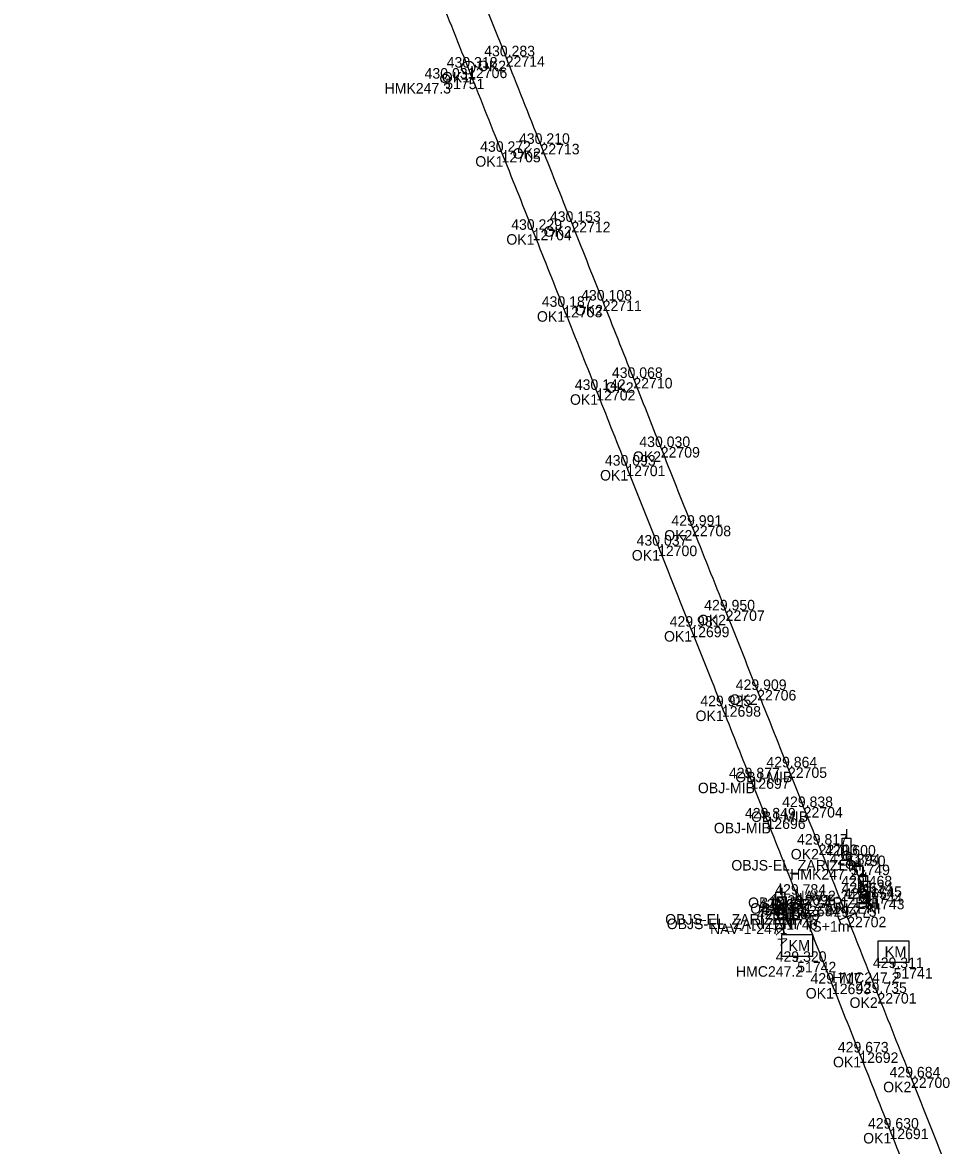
# Model space of a CAD drawing. Extents: x -678609 to -677678, y -1092434 to -1090394.
# Drawn here: x -678173.6 to -678067.3, y -1092180.5 to -1092052.4 of the extents above; entities that cross this region are included whole.
import ezdxf

# ---------------------------------------------------------------- set-up
doc = ezdxf.new("R2010")
doc.units = 0
for name, color, linetype in [('Vrstva 1', 7, 'Continuous'), ('Vrstva 3', 7, 'Continuous'), ('Vrstva 50', 7, 'Continuous'), ('Vrstva 6', 7, 'Continuous'), ('Vrstva 60', 7, 'Continuous'), ('Vrstva 61', 7, 'Continuous'), ('Vrstva 62', 7, 'Continuous'), ('Vrstva 7', 7, 'Continuous')]:
    doc.layers.add(name, color=color, linetype=linetype)

msp = doc.modelspace()

# ---------------------------------------------------------------- linework, layer by layer
at = {"layer": 'Vrstva 1'}
for points in [[(-677965.5, -1092428.88), (-677967.8, -1092425.54), (-677972.06, -1092419.07), (-677977.32, -1092410.57), (-677981.84, -1092402.75), (-677986.7, -1092393.7), (-677991.48, -1092384.16), (-677995.99, -1092374.55), (-678000.17, -1092365.13), (-678004.02, -1092356.1), (-678007.82, -1092346.9), (-678011.74, -1092337.16), (-678015.49, -1092327.76), (-678018.88, -1092319.21), (-678022.34, -1092310.49), (-678025.4, -1092302.78), (-678026.46, -1092300.1), (-678028.08, -1092296.04), (-678031.51, -1092287.37), (-678035.08, -1092278.36), (-678038.67, -1092269.33), (-678042.19, -1092260.44), (-678045.92, -1092251.04), (-678049.17, -1092242.84), (-678052.72, -1092233.88), (-678056.52, -1092224.29), (-678060.13, -1092215.17), (-678063.85, -1092205.78), (-678067.58, -1092196.38), (-678071.23, -1092187.17), (-678074.63, -1092178.59), (-678078.07, -1092169.9), (-678081.19, -1092162.05), (-678084.71, -1092153.16), (-678085.21, -1092151.9), (-678088.66, -1092143.2), (-678090.49, -1092138.62), (-678093.75, -1092130.39), (-678097.35, -1092121.32), (-678101.03, -1092112.07), (-678104.65, -1092102.94), (-678108.08, -1092094.3), (-678111.85, -1092084.82), (-678115.34, -1092076.03), (-678118.88, -1092067.13), (-678122.7, -1092057.52), (-678126.45, -1092048.08), (-678130.12, -1092038.85), (-678134.04, -1092029), (-678137.7, -1092019.78), (-678141.32, -1092010.68), (-678144.94, -1092001.55), (-678148.54, -1091992.51), (-678152.22, -1091983.22), (-678155.78, -1091974.26), (-678159.37, -1091965.23), (-678163.15, -1091955.67), (-678166.8, -1091946.49), (-678170.64, -1091936.84), (-678174.45, -1091927.39), (-678178.21, -1091918.23), (-678182.03, -1091909.19), (-678185.86, -1091900.36), (-678190.3, -1091890.41), (-678194.61, -1091881.04), (-678198.42, -1091872.99), (-678201.55, -1091866.52), (-678205.76, -1091857.98), (-678210.04, -1091849.52), (-678214.14, -1091841.6), (-678218.68, -1091833.02), (-678223.39, -1091824.3), (-678228.11, -1091815.74), (-678232.89, -1091807.24), (-678237.68, -1091798.82), (-678242.57, -1091790.27), (-678247.48, -1091781.7), (-678252.5, -1091772.96), (-678257.41, -1091764.41), (-678262.3, -1091755.91), (-678267.38, -1091747.08), (-678272.06, -1091738.95), (-678276.67, -1091730.93), (-678281, -1091723.4), (-678285.64, -1091715.33), (-678290.57, -1091706.75), (-678295.17, -1091698.74), (-678299.18, -1091691.75), (-678304.61, -1091682.28), (-678309.18, -1091674.33), (-678309.94, -1091673.01), (-678310.56, -1091671.92), (-678316.58, -1091661.44), (-678321.55, -1091652.79), (-678326.07, -1091644.94), (-678331.1, -1091636.19), (-678336.13, -1091627.42), (-678341.16, -1091618.67), (-678346.24, -1091609.83), (-678351.2, -1091601.19), (-678356.26, -1091592.39), (-678361.27, -1091583.68), (-678366.29, -1091574.95), (-678371.38, -1091566.09), (-678376.48, -1091557.23), (-678380.94, -1091549.47), (-678384.95, -1091542.5), (-678389.88, -1091533.92), (-678391.41, -1091531.24), (-678395.31, -1091524.46), (-678398.31, -1091519.22), (-678402.19, -1091512.46), (-678406.98, -1091504.09), (-678412.06, -1091495.21), (-678417.07, -1091486.44), (-678421.59, -1091478.47), (-678426.39, -1091469.86), (-678431.19, -1091461.01), (-678435.59, -1091452.6), (-678440.54, -1091442.69), (-678444.84, -1091433.53), (-678448.93, -1091424.07), (-678452.67, -1091414.65), (-678456.15, -1091404.93), (-678459.23, -1091395.35), (-678461.83, -1091386.29), (-678463.33, -1091380.53), (-678465.42, -1091371.56), (-678467.31, -1091362.18), (-678468.87, -1091352.97), (-678470.15, -1091343.72), (-678471.15, -1091334.55), (-678471.89, -1091325.25), (-678472.38, -1091315.14), (-678472.53, -1091305.81), (-678472.39, -1091295.81), (-678471.98, -1091285.84), (-678471.34, -1091275.9), (-678470.53, -1091266.07), (-678469.61, -1091256.67), (-678468.46, -1091246.14), (-678467.2, -1091235.36), (-678466.06, -1091225.73), (-678464.97, -1091216.57), (-678463.79, -1091206.63), (-678462.6, -1091196.46), (-678461.48, -1091186.51), (-678460.53, -1091177.26), (-678460.07, -1091172.27), (-678459.6, -1091166.76), (-678458.93, -1091157.15), (-678458.54, -1091149.43), (-678458.26, -1091139.81), (-678458.24, -1091130.03), (-678458.46, -1091121.76), (-678458.96, -1091112.72), (-678459.56, -1091105.42), (-678460.03, -1091100.7), (-678460.44, -1091097.18), (-678461.42, -1091089.83), (-678462.92, -1091080.59), (-678464.88, -1091070.5), (-678465.87, -1091066.01), (-678468.24, -1091056.34), (-678470.96, -1091046.62), (-678473.78, -1091037.66), (-678476.99, -1091028.33), (-678480.32, -1091019.35), (-678483.95, -1091010.17), (-678487.77, -1091000.93), (-678492.09, -1090990.94), (-678495.91, -1090982.33), (-678497.23, -1090979.39), (-678500.62, -1090971.85), (-678504.73, -1090962.75), (-678508.48, -1090954.44), (-678512.89, -1090944.72), (-678517.19, -1090935.17), (-678521.19, -1090926.12), (-678525.01, -1090917.23), (-678528.92, -1090907.75), (-678532.48, -1090898.64), (-678535.33, -1090890.88), (-678536.98, -1090886.19), (-678540.17, -1090876.47), (-678543.06, -1090866.93), (-678545.5, -1090858.15), (-678547.9, -1090848.75), (-678550.22, -1090838.91), (-678552.41, -1090829.04), (-678553.21, -1090825.32), (-678554.73, -1090818.04), (-678556.89, -1090807.48), (-678558.82, -1090797.84), (-678560.45, -1090789.69), (-678561.92, -1090782.3), (-678563.92, -1090772.26), (-678565.62, -1090763.66), (-678567.4, -1090754.78), (-678569.24, -1090745.59), (-678571.09, -1090736.37), (-678573.01, -1090726.79), (-678574.94, -1090717.24), (-678576.9, -1090707.5), (-678578.79, -1090698.06), (-678580.69, -1090688.61), (-678582.63, -1090679), (-678584.57, -1090669.32), (-678586.61, -1090659.12), (-678588.6, -1090649.18), (-678590.47, -1090639.75), (-678592.41, -1090629.68), (-678594.08, -1090620.48), (-678595.57, -1090611.73), (-678596.96, -1090602.7), (-678598.18, -1090593.61), (-678598.92, -1090587.15), (-678599.86, -1090577.04), (-678600.45, -1090567.62), (-678600.74, -1090558.34), (-678600.75, -1090549.35), (-678600.47, -1090539.84), (-678599.88, -1090530.15), (-678599.15, -1090521.99), (-678598.15, -1090513.61), (-678597.58, -1090509.5), (-678596.28, -1090501.33), (-678594.49, -1090491.96), (-678592.38, -1090482.44), (-678589.8, -1090472.45), (-678586.94, -1090462.72), (-678583.68, -1090452.87), (-678579.95, -1090442.85), (-678576.03, -1090433.29), (-678571.81, -1090423.92), (-678567.43, -1090415), (-678562.94, -1090406.55), (-678558.47, -1090398.73), (-678556.06, -1090394.72)], [(-677960.41, -1092428.88), (-677963.18, -1092424.89), (-677968.58, -1092416.71), (-677973.83, -1092408.16), (-677978.65, -1092399.73), (-677983.17, -1092391.19), (-677987.58, -1092382.29), (-677991.66, -1092373.51), (-677995.54, -1092364.73), (-677999.48, -1092355.45), (-678003, -1092346.86), (-678006.4, -1092338.41), (-678008.07, -1092334.22), (-678011.06, -1092326.67), (-678014.79, -1092317.28), (-678018.17, -1092308.77), (-678021.37, -1092300.71), (-678022.15, -1092298.75), (-678025.47, -1092290.39), (-678029, -1092281.48), (-678032.79, -1092271.95), (-678036.42, -1092262.78), (-678040.08, -1092253.55), (-678043.64, -1092244.58), (-678046.8, -1092236.63), (-678050.2, -1092228.09), (-678054.05, -1092218.4), (-678057.87, -1092208.77), (-678061.64, -1092199.28), (-678064.93, -1092190.99), (-678068.51, -1092181.96), (-678072.17, -1092172.75), (-678076, -1092163.12), (-678079.45, -1092154.42), (-678082.71, -1092146.18), (-678084.42, -1092141.9), (-678086.21, -1092137.37), (-678089.72, -1092128.54), (-678093.32, -1092119.46), (-678097.16, -1092109.8), (-678100.72, -1092100.82), (-678103.85, -1092092.93), (-678107.35, -1092084.1), (-678110.92, -1092075.12), (-678114.45, -1092066.22), (-678118.41, -1092056.23), (-678122.02, -1092047.13), (-678125.64, -1092038.01), (-678129.26, -1092028.91), (-678132.87, -1092019.79), (-678136.68, -1092010.21), (-678140.28, -1092001.13), (-678143.89, -1091992.04), (-678147.54, -1091982.83), (-678151.47, -1091972.91), (-678155.19, -1091963.55), (-678158.5, -1091955.23), (-678162.14, -1091946.1), (-678165.94, -1091936.55), (-678169.61, -1091927.42), (-678172.98, -1091919.18), (-678176.44, -1091910.89), (-678180.32, -1091901.84), (-678184.49, -1091892.39), (-678188.93, -1091882.59), (-678193.21, -1091873.41), (-678197.78, -1091863.91), (-678202.15, -1091855.03), (-678206.56, -1091846.3), (-678211.05, -1091837.64), (-678215.66, -1091828.96), (-678220.33, -1091820.38), (-678225.04, -1091811.91), (-678229.83, -1091803.42), (-678234.98, -1091794.42), (-678239.05, -1091787.33), (-678241.84, -1091782.5), (-678246.33, -1091774.68), (-678251.23, -1091766.16), (-678256.35, -1091757.27), (-678261.45, -1091748.4), (-678266.63, -1091739.38), (-678271.03, -1091731.75), (-678275.99, -1091723.11), (-678281.08, -1091714.25), (-678285.98, -1091705.75), (-678290.88, -1091697.22), (-678295.45, -1091689.28), (-678300.01, -1091681.35), (-678300.91, -1091679.77), (-678305.04, -1091672.59), (-678308.7, -1091666.23), (-678313.56, -1091657.79), (-678316.07, -1091653.42), (-678316.99, -1091651.81), (-678322.04, -1091643.03), (-678327.11, -1091634.21), (-678332.27, -1091625.24), (-678337.32, -1091616.47), (-678342.33, -1091607.74), (-678347.33, -1091599.07), (-678352.43, -1091590.19), (-678357.51, -1091581.37), (-678362.52, -1091572.64), (-678367.56, -1091563.89), (-678372.6, -1091555.12), (-678377.69, -1091546.26), (-678382.67, -1091537.58), (-678387.77, -1091528.7), (-678389.17, -1091526.27), (-678390.17, -1091524.53), (-678393.18, -1091519.29), (-678397.89, -1091511.08), (-678402.8, -1091502.52), (-678408.01, -1091493.44), (-678412.94, -1091484.8), (-678417.67, -1091476.44), (-678422.72, -1091467.34), (-678425.17, -1091462.84), (-678430.24, -1091453.27), (-678432.13, -1091449.6), (-678436.36, -1091441.06), (-678440.36, -1091432.52), (-678444.3, -1091423.5), (-678448.14, -1091413.92), (-678451.67, -1091404.2), (-678454.52, -1091395.48), (-678456.78, -1091387.89), (-678459.36, -1091378.14), (-678461.46, -1091369.04), (-678463.24, -1091360.11), (-678464.77, -1091350.94), (-678466.09, -1091341.11), (-678467.05, -1091331.45), (-678467.74, -1091321.16), (-678468.06, -1091312.46), (-678468.13, -1091302.67), (-678467.92, -1091292.89), (-678467.75, -1091288.5), (-678467.24, -1091279.36), (-678466.65, -1091271.3), (-678465.8, -1091261.65), (-678464.83, -1091252.21), (-678464.22, -1091246.73), (-678463.17, -1091237.54), (-678462.04, -1091228.08), (-678460.89, -1091218.47), (-678459.79, -1091209.09), (-678458.69, -1091199.72), (-678457.61, -1091190.23), (-678456.66, -1091181.26), (-678456.28, -1091177.45), (-678455.95, -1091173.93), (-678455.21, -1091164.81), (-678454.58, -1091155.4), (-678454.12, -1091145.39), (-678453.9, -1091135.42), (-678453.98, -1091125.41), (-678454.4, -1091115.15), (-678455.19, -1091104.66), (-678455.67, -1091099.79), (-678456.77, -1091090.92), (-678457.24, -1091087.61), (-678458, -1091082.76), (-678459.78, -1091072.93), (-678461.55, -1091064.59), (-678463.75, -1091055.56), (-678466.3, -1091046.3), (-678469.14, -1091037.12), (-678472.3, -1091027.84), (-678475.73, -1091018.55), (-678479.35, -1091009.34), (-678482.78, -1091001.05), (-678486.39, -1090992.59), (-678490.2, -1090983.9), (-678491.75, -1090980.39), (-678492.98, -1090977.64), (-678496.18, -1090970.51), (-678500.43, -1090961.06), (-678504.03, -1090953.05), (-678508.11, -1090943.95), (-678512.14, -1090934.91), (-678516.17, -1090925.76), (-678520.15, -1090916.48), (-678524.11, -1090906.91), (-678527.45, -1090898.46), (-678529.96, -1090891.82), (-678532.42, -1090885.01), (-678535.4, -1090876.25), (-678538.3, -1090867), (-678541.15, -1090857.05), (-678543.63, -1090847.53), (-678545.8, -1090838.5), (-678548.27, -1090827.42), (-678548.84, -1090824.71), (-678550.27, -1090817.89), (-678552.12, -1090808.75), (-678554.09, -1090798.9), (-678556.12, -1090788.74), (-678556.56, -1090786.52), (-678557.74, -1090780.65), (-678559.41, -1090772.28), (-678561.24, -1090763.16), (-678563.16, -1090753.57), (-678565.21, -1090743.33), (-678567.13, -1090733.77), (-678569.13, -1090723.69), (-678570.72, -1090715.75), (-678572.44, -1090707.11), (-678574.33, -1090697.58), (-678575.5, -1090691.73), (-678576.87, -1090684.87), (-678578.68, -1090675.8), (-678580.42, -1090667.12), (-678582.34, -1090657.49), (-678584.31, -1090647.61), (-678586.28, -1090637.64), (-678588.2, -1090627.59), (-678589.96, -1090617.89), (-678591.58, -1090608.06), (-678593.06, -1090598.01), (-678594.31, -1090587.86), (-678595.29, -1090577.74), (-678595.95, -1090567.92), (-678596.27, -1090558.34), (-678596.28, -1090548.9), (-678595.99, -1090539.16), (-678595.39, -1090529.68), (-678594.52, -1090520.33), (-678593.84, -1090514.64), (-678593.37, -1090511.09), (-678591.87, -1090501.55), (-678590.51, -1090494.26), (-678588.64, -1090485.54), (-678587.94, -1090482.56), (-678585.53, -1090473.2), (-678582.78, -1090463.82), (-678579.92, -1090455.12), (-678576.62, -1090446.03), (-678572.81, -1090436.54), (-678568.84, -1090427.54), (-678564.34, -1090418.19), (-678559.62, -1090409.18), (-678555.08, -1090401.15), (-678551.2, -1090394.72)]]:
    msp.add_spline(points, degree=3, dxfattribs=at)
at = {"layer": 'Vrstva 3'}
for p, q in [((-678085.83, -1092153.06), (-678085.46, -1092153.99)), ((-678083.78, -1092152.79), (-678085.64, -1092153.52)), ((-678083.97, -1092152.32), (-678083.6, -1092153.25)), ((-678080.56, -1092154.32), (-678080.19, -1092155.25)), ((-678078.52, -1092154.05), (-678080.38, -1092154.79)), ((-678078.7, -1092153.59), (-678078.33, -1092154.52))]:
    msp.add_line(p, q, dxfattribs=at)
at = {"layer": 'Vrstva 50'}
for p, q in [((-678079.54, -1092144.44), (-678079.54, -1092145.44)), ((-678079.49, -1092147.44), (-678079.59, -1092147.44)), ((-678077.63, -1092148.72), (-678077.63, -1092149.72)), ((-678077.38, -1092149.37), (-678077.38, -1092150.37)), ((-678087.09, -1092150.61), (-678087.09, -1092151.61)), ((-678086.91, -1092151.13), (-678086.91, -1092152.13)), ((-678077.58, -1092151.72), (-678077.68, -1092151.72)), ((-678077.33, -1092152.37), (-678077.43, -1092152.37)), ((-678087.04, -1092153.61), (-678087.14, -1092153.61)), ((-678086.86, -1092154.13), (-678086.96, -1092154.13))]:
    msp.add_line(p, q, dxfattribs=at)
for points in [[(-678080.05, -1092147.44), (-678080.04, -1092145.44), (-678079.03, -1092145.44), (-678079.03, -1092147.44)], [(-678078.13, -1092151.72), (-678078.13, -1092149.72), (-678077.12, -1092149.72), (-678077.12, -1092151.72)], [(-678077.89, -1092152.37), (-678077.88, -1092150.37), (-678076.88, -1092150.37), (-678076.88, -1092152.37)], [(-678087.59, -1092153.61), (-678087.59, -1092151.61), (-678086.58, -1092151.61), (-678086.58, -1092153.61)], [(-678087.42, -1092154.13), (-678087.41, -1092152.13), (-678086.4, -1092152.13), (-678086.4, -1092154.13)]]:
    msp.add_lwpolyline(points, dxfattribs=at)
for centre in [(-678079.54, -1092147.44), (-678077.63, -1092151.72), (-678077.38, -1092152.37), (-678087.09, -1092153.61), (-678086.91, -1092154.13)]:
    msp.add_circle(centre, 0.506, dxfattribs=at)
at = {"layer": 'Vrstva 6'}
for p, q in [((-678078.48, -1092149.14), (-678077.67, -1092150.95)), ((-678078.12, -1092151.15), (-678077.21, -1092150.74)), ((-678077.23, -1092150.71), (-678078.11, -1092151.18)), ((-678076.73, -1092152.69), (-678077.67, -1092150.95)), ((-678088.1, -1092152.88), (-678087.3, -1092154.69)), ((-678087.75, -1092154.89), (-678086.84, -1092154.48)), ((-678086.84, -1092154.49), (-678087.75, -1092154.89)), ((-678086.5, -1092156.5), (-678087.3, -1092154.69))]:
    msp.add_line(p, q, dxfattribs=at)
at = {"layer": 'Vrstva 60'}
for p, q in [((-678118.41, -1092056.23), (-678118.41, -1092056.23)), ((-678122.7, -1092057.52), (-678122.7, -1092057.52)), ((-678125.31, -1092058.78), (-678125.31, -1092058.78)), ((-678118.88, -1092067.13), (-678118.88, -1092067.13)), ((-678114.45, -1092066.22), (-678114.45, -1092066.22)), ((-678110.92, -1092075.12), (-678110.92, -1092075.12)), ((-678115.34, -1092076.03), (-678115.34, -1092076.03)), ((-678107.35, -1092084.1), (-678107.35, -1092084.1)), ((-678111.85, -1092084.82), (-678111.85, -1092084.82)), ((-678103.85, -1092092.93), (-678103.85, -1092092.93)), ((-678108.08, -1092094.3), (-678108.08, -1092094.3)), ((-678100.72, -1092100.82), (-678100.72, -1092100.82)), ((-678104.65, -1092102.94), (-678104.65, -1092102.94)), ((-678097.16, -1092109.8), (-678097.16, -1092109.8)), ((-678101.03, -1092112.07), (-678101.03, -1092112.07)), ((-678093.32, -1092119.46), (-678093.32, -1092119.46)), ((-678097.35, -1092121.32), (-678097.35, -1092121.32)), ((-678089.72, -1092128.54), (-678089.72, -1092128.54)), ((-678093.75, -1092130.39), (-678093.75, -1092130.39)), ((-678086.21, -1092137.37), (-678086.21, -1092137.37)), ((-678090.49, -1092138.62), (-678090.49, -1092138.62)), ((-678084.42, -1092141.9), (-678084.42, -1092141.9)), ((-678088.66, -1092143.2), (-678088.66, -1092143.2)), ((-678082.71, -1092146.18), (-678082.71, -1092146.18)), ((-678079.54, -1092147.44), (-678079.54, -1092147.44)), ((-678079.04, -1092148.47), (-678079.04, -1092148.47)), ((-678085.21, -1092151.9), (-678085.21, -1092151.9)), ((-678077.67, -1092150.95), (-678077.67, -1092150.95)), ((-678077.63, -1092151.72), (-678077.63, -1092151.72)), ((-678084.71, -1092153.16), (-678084.71, -1092153.16)), ((-678077.38, -1092152.37), (-678077.38, -1092152.37)), ((-678087.09, -1092153.61), (-678087.09, -1092153.61)), ((-678086.91, -1092154.13), (-678086.91, -1092154.13)), ((-678079.45, -1092154.42), (-678079.45, -1092154.42)), ((-678087.3, -1092154.69), (-678087.3, -1092154.69)), ((-678085.16, -1092159.56), (-678085.16, -1092159.56)), ((-678074.16, -1092160.27), (-678074.16, -1092160.27)), ((-678081.19, -1092162.05), (-678081.19, -1092162.05)), ((-678076, -1092163.12), (-678076, -1092163.12)), ((-678078.07, -1092169.9), (-678078.07, -1092169.9)), ((-678072.17, -1092172.75), (-678072.17, -1092172.75)), ((-678074.63, -1092178.59), (-678074.63, -1092178.59))]:
    msp.add_line(p, q, dxfattribs=at)
at = {"layer": 'Vrstva 7'}
for p, q in [((-678125.36, -1092058.78), (-678125.26, -1092058.78)), ((-678079.09, -1092148.47), (-678078.99, -1092148.47)), ((-678085.16, -1092159.56), (-678085.16, -1092158.94)), ((-678074.16, -1092160.27), (-678074.16, -1092159.65))]:
    msp.add_line(p, q, dxfattribs=at)
for points in [[(-678086.9, -1092158.94), (-678086.9, -1092156.46), (-678083.41, -1092156.46), (-678083.41, -1092158.94)], [(-678075.9, -1092159.65), (-678075.9, -1092157.17), (-678072.41, -1092157.17), (-678072.41, -1092159.65)]]:
    msp.add_lwpolyline(points, close=True, dxfattribs=at)
for centre, radius in [((-678122.7, -1092057.52), 0.75), ((-678125.31, -1092058.78), 0.5), ((-678079.04, -1092148.47), 0.5)]:
    msp.add_circle(centre, radius, dxfattribs=at)

# ---------------------------------------------------------------- texts
at = {"layer": 'Vrstva 6'}
for rotation, p in [(114.2139, (-678076.76, -1092150.54)), (114.1044, (-678086.38, -1092154.28)), (298.1762, (-678078.55, -1092151.42)), (293.6861, (-678088.21, -1092155.09))]:
    msp.add_text('  A A ', height=1, rotation=rotation, dxfattribs=at).set_placement(p)
at = {"layer": 'Vrstva 60'}
for s, p in [('22714', (-678118.41, -1092057.43)), ('12706', (-678122.7, -1092058.72)), ('51751', (-678125.31, -1092059.98)), ('12705', (-678118.88, -1092068.33)), ('22713', (-678114.45, -1092067.42)), ('22712', (-678110.92, -1092076.32)), ('12704', (-678115.34, -1092077.23)), ('22711', (-678107.35, -1092085.3)), ('12703', (-678111.85, -1092086.02)), ('22710', (-678103.85, -1092094.13)), ('12702', (-678108.08, -1092095.5)), ('22709', (-678100.72, -1092102.02)), ('12701', (-678104.65, -1092104.14)), ('22708', (-678097.16, -1092111)), ('12700', (-678101.03, -1092113.27)), ('22707', (-678093.32, -1092120.66)), ('12699', (-678097.35, -1092122.52)), ('22706', (-678089.72, -1092129.74)), ('12698', (-678093.75, -1092131.59)), ('22705', (-678086.21, -1092138.57)), ('12697', (-678090.49, -1092139.82)), ('22704', (-678084.42, -1092143.1)), ('12696', (-678088.66, -1092144.4)), ('22703', (-678082.71, -1092147.38)), ('51750', (-678079.54, -1092148.64)), ('51749', (-678079.04, -1092149.67)), ('12695', (-678085.21, -1092153.1)), ('51745', (-678077.67, -1092152.15)), ('51744', (-678077.63, -1092152.92)), ('12694', (-678084.71, -1092154.36)), ('51743', (-678077.38, -1092153.57)), ('51748', (-678087.09, -1092154.81)), ('51747', (-678086.91, -1092155.33)), ('22702', (-678079.45, -1092155.62)), ('51746', (-678087.3, -1092155.89)), ('51742', (-678085.16, -1092160.76)), ('51741', (-678074.16, -1092161.47)), ('12693', (-678081.19, -1092163.25)), ('22701', (-678076, -1092164.32)), ('12692', (-678078.07, -1092171.1)), ('22700', (-678072.17, -1092173.95)), ('12691', (-678074.63, -1092179.79))]:
    msp.add_text(s, height=1.2, dxfattribs=at).set_placement(p)
at = {"layer": 'Vrstva 61'}
for s, p in [('430.283', (-678120.87, -1092056.23)), ('430.318', (-678125.15, -1092057.52)), ('430.031', (-678127.67, -1092058.78)), ('430.272', (-678121.33, -1092067.13)), ('430.210', (-678116.9, -1092066.22)), ('430.229', (-678117.79, -1092076.03)), ('430.153', (-678113.37, -1092075.12)), ('430.187', (-678114.3, -1092084.82)), ('430.108', (-678109.81, -1092084.1)), ('430.068', (-678106.3, -1092092.93)), ('430.142', (-678110.53, -1092094.3)), ('430.030', (-678103.17, -1092100.82)), ('430.093', (-678107.1, -1092102.94)), ('429.991', (-678099.51, -1092109.8)), ('430.037', (-678103.48, -1092112.07)), ('429.950', (-678095.77, -1092119.46)), ('429.981', (-678099.71, -1092121.32)), ('429.909', (-678092.17, -1092128.54)), ('429.925', (-678096.21, -1092130.39)), ('429.864', (-678088.67, -1092137.37)), ('429.877', (-678092.94, -1092138.62)), ('429.838', (-678086.87, -1092141.9)), ('429.849', (-678091.12, -1092143.2)), ('429.817', (-678085.17, -1092146.18)), ('429.600', (-678081.99, -1092147.44)), ('429.894', (-678081.49, -1092148.47)), ('429.784', (-678087.66, -1092151.9)), ('429.468', (-678080.12, -1092150.95)), ('429.624', (-678080.08, -1092151.72)), ('429.773', (-678087.17, -1092153.16)), ('429.654', (-678079.83, -1092152.37)), ('429.655', (-678089.55, -1092153.61)), ('429.651', (-678089.27, -1092154.13)), ('429.775', (-678081.9, -1092154.42)), ('429.506', (-678089.75, -1092154.69)), ('429.320', (-678087.61, -1092159.56)), ('429.311', (-678076.52, -1092160.27)), ('429.717', (-678083.64, -1092162.05)), ('429.735', (-678078.45, -1092163.12)), ('429.673', (-678080.52, -1092169.9)), ('429.684', (-678074.62, -1092172.75)), ('429.630', (-678077.08, -1092178.59))]:
    msp.add_text(s, height=1.2, dxfattribs=at).set_placement(p)
at = {"layer": 'Vrstva 62'}
for s, p in [('OK2', (-678121.59, -1092057.93)), ('OK1', (-678125.7, -1092059.22)), ('HMK247.3', (-678132.24, -1092060.48)), ('OK2', (-678117.62, -1092067.92)), ('OK1', (-678121.88, -1092068.83)), ('OK2', (-678114.09, -1092076.82)), ('OK1', (-678118.34, -1092077.73)), ('OK1', (-678114.85, -1092086.52)), ('OK2', (-678110.53, -1092085.8)), ('OK2', (-678107.03, -1092094.63)), ('OK1', (-678111.08, -1092096)), ('OK2', (-678103.9, -1092102.52)), ('OK1', (-678107.65, -1092104.64)), ('OK2', (-678100.33, -1092111.5)), ('OK1', (-678104.03, -1092113.77)), ('OK2', (-678096.5, -1092121.16)), ('OK1', (-678100.35, -1092123.02)), ('OK2', (-678092.89, -1092130.24)), ('OK1', (-678096.75, -1092132.09)), ('OBJ-MIB', (-678092.22, -1092139.07)), ('OBJ-MIB', (-678096.49, -1092140.32)), ('OBJ-MIB', (-678090.42, -1092143.6)), ('OBJ-MIB', (-678094.67, -1092144.9)), ('OK2', (-678085.89, -1092147.88)), ('OBJS-EL_ZARIZENI', (-678092.67, -1092149.14)), ('HMK247.2', (-678085.96, -1092150.17)), ('NAV-2-2471', (-678085.48, -1092152.65)), ('OBJS-EL_ZARIZENI', (-678090.76, -1092153.42)), ('OBJS-EL_ZARIZENI', (-678090.52, -1092154.07)), ('OK1', (-678088.21, -1092153.6)), ('OBJS-EL_ZARIZENI', (-678100.22, -1092155.31)), ('OBJS-EL_ZARIZENI', (-678100.04, -1092155.83)), ('IS', (-678086.44, -1092154.86)), ('NAV-1-2471', (-678095.1, -1092156.39)), ('IS+1m', (-678083.87, -1092156.12)), ('HMC247.2', (-678092.15, -1092161.26)), ('HMC247.2', (-678081.16, -1092161.97)), ('OK1', (-678084.18, -1092163.75)), ('OK2', (-678079.18, -1092164.82)), ('OK1', (-678081.07, -1092171.6)), ('OK2', (-678075.35, -1092174.45)), ('OK1', (-678077.63, -1092180.29))]:
    msp.add_text(s, height=1.2, dxfattribs=at).set_placement(p)
at = {"layer": 'Vrstva 7'}
for p in [(-678086.17, -1092158.32), (-678075.18, -1092159.03)]:
    msp.add_text('KM', height=1.247, dxfattribs=at).set_placement(p)

doc.saveas('drawing.dxf')
